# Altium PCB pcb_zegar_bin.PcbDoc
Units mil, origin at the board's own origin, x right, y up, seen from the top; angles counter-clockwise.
Board outline 4065 x 2637.8 mil, 2 copper layers (Top Layer, Bottom Layer); 55 components, 35 nets, 155 pads, 4 vias.
Unrouted connection lines stored in the file: 2.
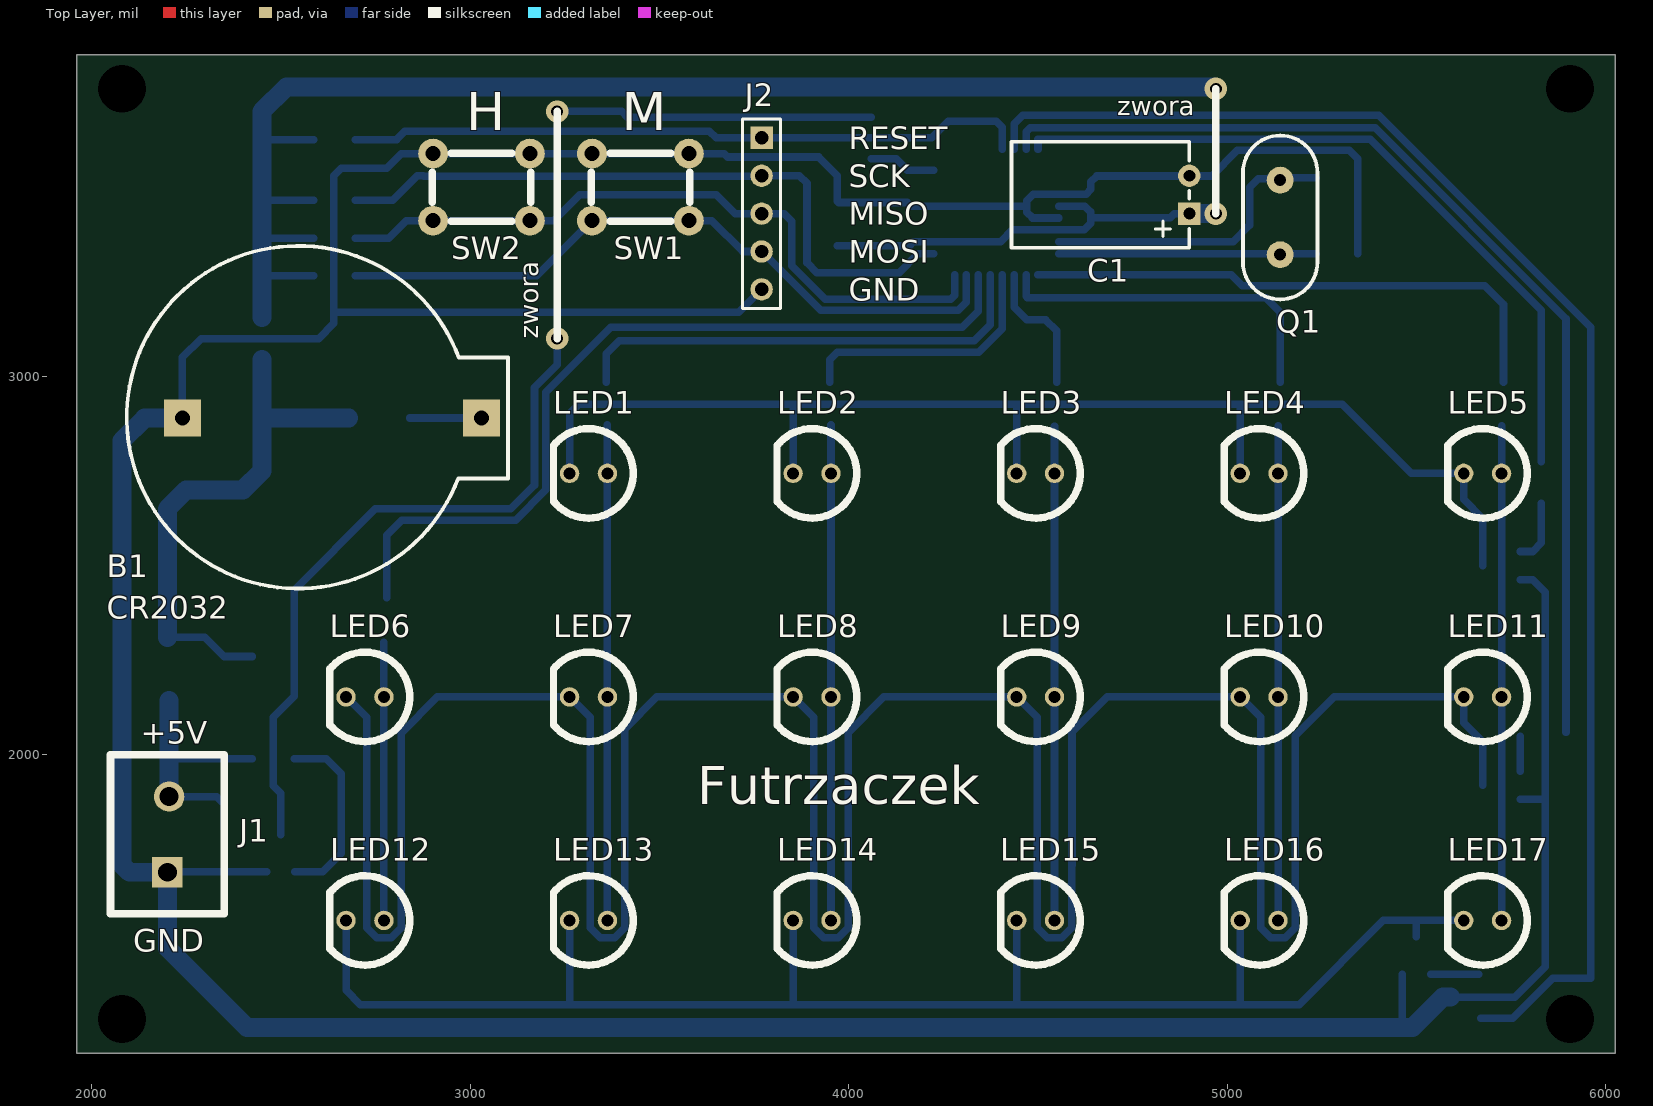
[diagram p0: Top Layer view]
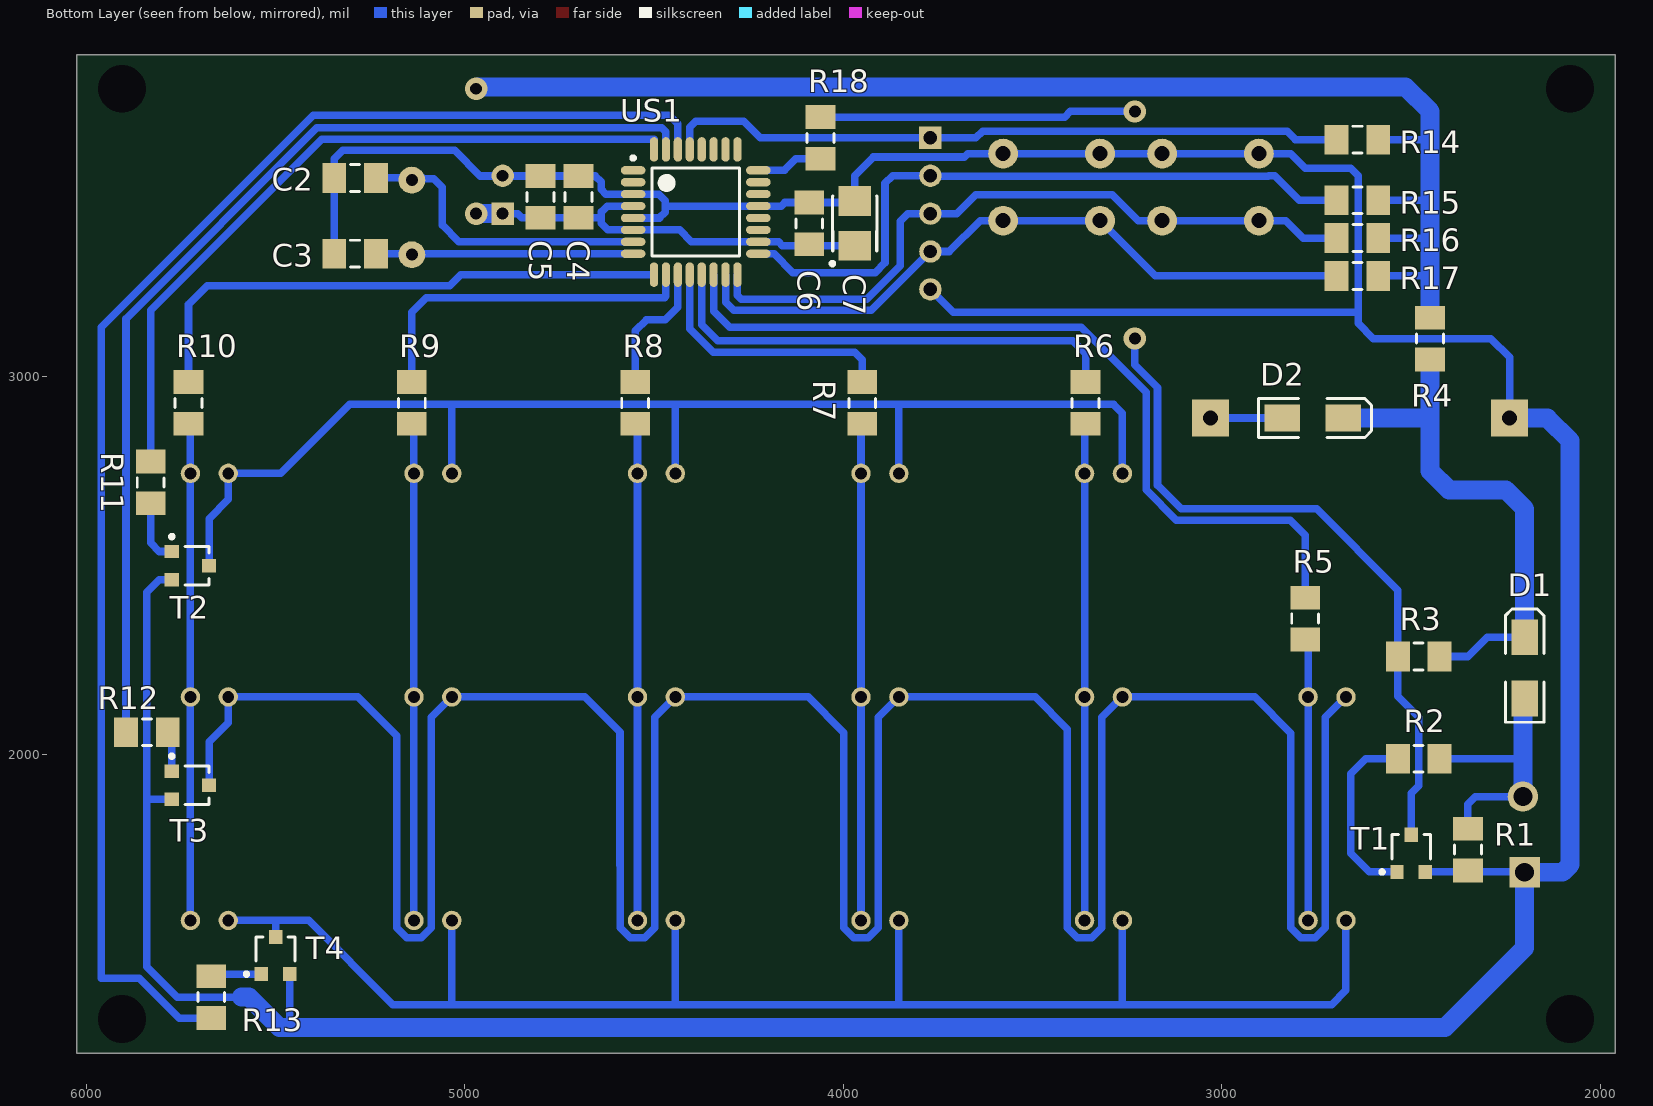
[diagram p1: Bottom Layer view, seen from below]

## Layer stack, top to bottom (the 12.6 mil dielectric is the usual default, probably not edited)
Top Layer: signal copper 1.4
Dielectric: dielectric 12.6, FR-4, Dk 4.8
Bottom Layer: signal copper 1.4

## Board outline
1960.51,1212.2 1960.51,3850 6025.51,3850 6025.51,1212.2

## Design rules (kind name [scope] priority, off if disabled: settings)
Clearance [All] p1: gap=10
PolygonConnect [All] p1: connectstyle=Relief reliefconductorwidth=10 reliefentries=4 polygonreliefangle="90 Angle"
RoutingVias [All] p1: holewidth=28 width=50 viastyle="Through Hole" minholewidth=28 minwidth=50 maxholewidth=28 maxwidth=50
SilkscreenOverComponentPads [All] p1: minsilkscreentomaskgap=10
SolderMaskExpansion [All] p1: expansion=4
Width [All] p1: maxlimit=100 minlimit=10 preferedwidth=20
27 further rules are at their usual default settings.

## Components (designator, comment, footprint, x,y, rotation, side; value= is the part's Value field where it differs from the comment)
B1 "CR2032" "CR20xx THT" 2550,2890 r0 top
C1 "220u/16V" "2,5/7mm le抗cy elektrolit" 4900,3480 r90 top
C2 "18p" MELF-1206 5290,3524.25 r180 bottom
C3 "18p" MELF-1206 5290,3324.25 r180 bottom
C4 "18p" MELF-1206 4700,3474.25 r270 bottom
C5 "100n" MELF-1206 4800,3474.25 r270 bottom
C6 "100n" MELF-1206 4090,3404.25 r270 bottom
C7 "22u/16V B" "Tantal B 3528-1411" 3970,3404.25 r90 bottom
D1 "BYS10-45" SMA 2200,2230 r90 bottom
D2 "BYS10-45" SMA 2760,2890 r180 bottom
J1 "ARK2" "ARK2 5mm" 2200,1790 r90 top
J2 "Header 5" HDR1X5 3770,3630 r270 top
LED1 "red" "LED 5mm" 3312.76,2743.86 r0 top
LED2 "red" "LED 5mm" 3903.31,2743.86 r0 top
LED3 "red" "LED 5mm" 4493.86,2743.86 r0 top
LED4 "red" "LED 5mm" 5084.41,2743.86 r0 top
LED5 "red" "LED 5mm" 5674.96,2743.86 r0 top
LED6 "green" "LED 5mm" 2722.2,2153.31 r0 top
LED7 "green" "LED 5mm" 3312.76,2153.31 r0 top
LED8 "green" "LED 5mm" 3903.31,2153.31 r0 top
LED9 "green" "LED 5mm" 4493.86,2153.31 r0 top
LED10 "green" "LED 5mm" 5084.41,2153.31 r0 top
LED11 "green" "LED 5mm" 5674.96,2153.31 r0 top
LED12 "yellow" "LED 5mm" 2722.2,1562.76 r0 top
LED13 "yellow" "LED 5mm" 3312.76,1562.76 r0 top
LED14 "yellow" "LED 5mm" 3903.31,1562.76 r0 top
LED15 "yellow" "LED 5mm" 4493.86,1562.76 r0 top
LED16 "yellow" "LED 5mm" 5084.41,1562.76 r0 top
LED17 "yellow" "LED 5mm" 5674.96,1562.76 r0 top
Q1 "4MHz" "kwarc 5mm" 5140,3420 r90 top
R1 "4,7k" MELF-1206 2350,1750 r90 bottom
R2 "4,7k" MELF-1206 2480,1990 r180 bottom
R3 "4,7k" MELF-1206 2480,2260 r180 bottom
R4 "0" MELF-1206 2450,3100 r270 bottom
R5 "180" MELF-1206 2780,2360 r90 bottom
R6 "180" MELF-1206 3360,2930 r90 bottom
R7 "180" MELF-1206 3950,2930 r90 bottom
R8 "180" MELF-1206 4550,2930 r90 bottom
R9 "180" MELF-1206 5140,2930 r90 bottom
R10 "180" MELF-1206 5730,2930 r90 bottom
R11 "4,7k" MELF-1206 5830,2720 r90 bottom
R12 "4,7k" MELF-1206 5840,2060 r0 bottom
R13 "4,7k" MELF-1206 5670,1360 r270 bottom
R14 "4,7k" MELF-1206 2641.81,3625.43 r180 bottom
R15 "4,7k" MELF-1206 2641.81,3465.43 r180 bottom
R16 "4,7k" MELF-1206 2641.81,3365.43 r180 bottom
R17 "4,7k" MELF-1206 2641.81,3265.43 r180 bottom
R18 "0" MELF-1206 4060,3630 r270 bottom
SW1 "sw 6x6" "tact switch 6x6" 3450,3500 r180 top
SW2 "sw 6x6" "tact switch 6x6" 3030,3500 r180 top
T1 "BC847" 318-08 2500,1740 r180 bottom
T2 "BC847" 318-08 5724.96,2500 r270 bottom
T3 "BC847" 318-08 5724.96,1920 r270 bottom
T4 "BC847" 318-08 5500,1470 r180 bottom
US1 "ATmega48V-10AU" 32A_N 4390,3434.25 r180 bottom

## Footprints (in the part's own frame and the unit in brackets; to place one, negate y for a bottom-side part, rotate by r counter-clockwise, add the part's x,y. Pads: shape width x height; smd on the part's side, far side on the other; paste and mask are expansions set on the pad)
"2,5/7mm le抗cy elektrolit" [mm]
  rect 1.5x1.5 hole 0.8: 1(-1.27,0)
  round 1.5 hole 0.8: 2(1.27,0)
  silkscreen extent -3.56,0 3.56,11.94
32A_N [mm] "Thin QFP, 32-Leads, Body 7x7mm, Pitch 0.8mm, IPC Medium Density"
  oval 1.65x0.55 smd: 1(-4.2,2.8) 2(-4.2,2) 3(-4.2,1.2) 4(-4.2,0.4) 5(-4.2,-0.4) 6(-4.2,-1.2) 7(-4.2,-2) 8(-4.2,-2.8) 17(4.2,-2.8) 18(4.2,-2) 19(4.2,-1.2) 20(4.2,-0.4) 21(4.2,0.4) 22(4.2,1.2) 23(4.2,2) 24(4.2,2.8)
  oval 0.55x1.65 smd: 9(-2.8,-4.2) 10(-2,-4.2) 11(-1.2,-4.2) 12(-0.4,-4.2) 13(0.4,-4.2) 14(1.2,-4.2) 15(2,-4.2) 16(2.8,-4.2) 25(2.8,4.2) 26(2,4.2) 27(1.2,4.2) 28(0.4,4.2) 29(-0.4,4.2) 30(-1.2,4.2) 31(-2,4.2) 32(-2.8,4.2)
  silkscreen extent -4.33,-2.95 2.95,3.75, body extent -3.5,-3.5 3.5,3.5, height 1.2
318-08 [mm] "SOT-23; 3 Leads; Body 3.0 x 2.6 mm, inc. leads (LxW max)"
  rect 0.9x0.95 smd: 1(-0.95,-1.25) 2(0.95,-1.25) 3(0,1.25)
  silkscreen extent -2.08,-1.37 1.3,1.25
"ARK2 5mm" [mil]
  rect 80x80 hole 50: 1(-100,0)
  round 80 hole 50: 2(100,-5)
  silkscreen extent -210,-150 210,150, body extent -220,-160 220,160, height 394
"CR20xx THT" [mm]
  rect 2.5x2.5 hole 1: 1(12.192,0) 2(-7.874,0)
  silkscreen extent -11.61,-11.44 13.97,11.55
HDR1X5 [mm] "Connector; Header; 5 Position"
  rect 1.5x1.5 hole 0.9: 1(0,0)
  round 1.5 hole 0.9: 2(2.54,0) 3(5.08,0) 4(7.62,0) 5(10.16,0)
  silkscreen extent -1.27,-1.27 11.43,1.27
"kwarc 5mm" [mm]
  round 1.8 hole 0.8: 1(-2.5,0) 2(2.5,0)
  silkscreen extent -5.5,-2.5 5.5,2.5
"LED 5mm" [mm]
  round 1.3 hole 0.8: A(1.27,0) K(-1.27,0)
  silkscreen extent -2.35,-3 3,3
MELF-1206 [mm] "Metal Electrode Face (MELF) Resistor; Body 3.2 x 1.8 mm (LxDia)"
  rect 1.6x2 smd: 1(-1.4,0) 2(1.4,0)
  silkscreen extent -0.3,-0.9 0.3,0.9, body extent -2.3,-1.1 2.3,1.1, height 1.85
SMA [mm] "DO-214-AC/SMA; 2 C-Bend Leads; Body 5 x 2.7 mm, inc. leads (LxW)"
  rect 2.4x1.8 smd: 1(-2.05,0) 2(2.05,0)
  silkscreen extent -3.65,-1.3 3.95,1.3
"tact switch 6x6" [mm]
  round 2 hole 1: 1(3.25,2.25) 2(3.25,-2.25) 3(-3.25,2.25) 4(-3.25,-2.25)
  silkscreen extent -3.3,-2.29 3.3,2.29
"Tantal B 3528-1411" [mm] "Capacitor, SM Tantalum; Body 3.5 x 2.8 mm (LxW typ)"
  rect 2x2.2 smd: 1(-1.5,0) 2(1.5,0)
  silkscreen extent -2.82,-1.5 1.85,1.63, body extent -2.6,-1.2 2.6,1.2, height 2.5

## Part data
B1: library part BAT
C1 C7: library part "kond biegunowy", "Polarized Capacitor"
C2 C3 C4 C5 C6: library part kondensator
D1 D2: library part 10MQ060N, "Schottky Rectifier"
J2: "Header, 5-Pin"
LED1 LED2 LED3 LED4 LED5 LED6 LED7 LED8 LED9 LED10 LED11 LED12 LED13 LED14 LED15 LED16 LED17: library part LED
Q1: library part kwarc
R1 R2 R3 R4 R5 R6 R7 R8 R9 R10 R11 R12 R13 R14 R15 R16 R17 R18: library part rezystor
SW1 SW2: library part switch
T1 T2 T3 T4: library part BC847ALT1, "General Purpose Transistor NPN Silicon"
US1: library part ATmega8-16AC, "8-Bit AVR Microcontroller with 8K Bytes of In-System Programmable Flash Memory"

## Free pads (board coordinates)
  round 0 hole 125.98: 0(2080.51,1302.2) 0(2080.51,3760) 0(5905.51,1302.2) 0(5905.51,3760)

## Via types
v1: diameter 59.06, hole 31.5, Top Layer to Bottom Layer, 4 vias

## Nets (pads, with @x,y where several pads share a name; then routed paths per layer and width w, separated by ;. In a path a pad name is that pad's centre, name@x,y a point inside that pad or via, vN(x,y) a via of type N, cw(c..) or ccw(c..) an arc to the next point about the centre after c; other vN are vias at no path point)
GND: B1.2 C1.2 C2.1 C3.1 C4.1 C5.1 C6.1 C7.2 J1.1 J2.5 R1.1 SW1.2 SW1.4 SW2.2 SW2.4 T1.2 T2.2 T3.2 T4.2 US1.3 US1.5 US1.21 | length 12382.3
  Bottom Layer w20: J1.1@2200.79,1690.79 T1.2 ; B1.2 2240,3050 2290,3100 2600,3100 2640,3140 2640,3170 ; J2.5 3710,3170 2640,3170 ; US1.5 4485.75,3418.5 4470,3434.25 4470,3454.25 ; C3.1 C2.1 5345.12,3574.88 5323.02,3596.98 5026.98,3596.98 4959.37,3529.37 C5.1 C4.1 4655.12,3529.37 4640,3514.25 4640,3494.25 4627.24,3481.5 US1.3 4487.24,3481.5 4470,3464.25 4470,3454.25 ; 5462.6,1297.4 T4.2 ; 5570,1360 5760,1360 5840,1440 5840,2430 5807.4,2462.6 T2.2 ; T3.2 5837.4,1882.6 ; 2640,3170 2640,3530 2660,3550 2780,3550 2818.58,3588.58 SW2.2 SW2.4 SW1.2 SW1.4 3671.42,3588.58 3680.47,3579.53 3920.47,3579.53 3970,3530 C7.2 3973.94,3459.37 C6.1 4154.88,3459.37 4164.25,3450 US1.21 4465.75,3450 4470,3454.25
  Bottom Layer w50: B1.2 2140,2890 2080,2830 2080,1710 2100,1690 J1.1 2200,1490 2410,1280 5490,1280 5570,1360 5590,1360
H: R11.2 US1.32 | length 1944.3
  Bottom Layer w20: US1.32 4500.24,3626.98 5378.16,3626.98 5830,3175.15 R11.2
M: R12.2 US1.31 | length 2778.6
  Bottom Layer w20: US1.31 4469.41,3600.28 4469.41,3646.39 4480,3656.98 5390.59,3656.98 5895.12,3152.46 R12.2
NetB1_1: B1.1 D2.1 | length 189.3
  Bottom Layer w20: D2.1 B1.1
NetC2_2: C2.2 Q1.2 US1.7 | length 808
  Bottom Layer w20: US1.7 5015.51,3355.51 5060,3400 5060,3500 5082.68,3522.68 5110,3522.68 5111.57,3524.25 C2.2
NetC3_2: C3.2 Q1.1 US1.8 | length 679.5
  Bottom Layer w20: US1.8 C3.2@5234.88,3324.02
NetD1_1: D1.1 J1.2 R1.2 R2.2 | length 692.3
  Bottom Layer w20: J1.2 2330,1890 2350,1870 R1.2 ; 2205,1990 R2.2
  Bottom Layer w50: J1.2 2205,1990 D1.1@2205,2144.29
NetD1_2: D1.2 D2.2 R3.2 R4.2 | length 1400.8
  Bottom Layer w20: D1.2 2299.29,2310.71 2350,2260 R3.2
  Bottom Layer w50: D1.2 2200,2650 2250,2700 2400,2700 2450,2750 2450,2890 ; R4.2 2450,2890 ; D2.2 2450,2890
NetJ2_1: J2.1 R14.1 US1.29 | length 1809.3
  Bottom Layer w20: R14.1 2805.43,3625.43 2827.95,3647.95 3632.05,3647.95 3650,3630 J2.1 4219.06,3630 4263.31,3674.25 4390,3674.25 4405.75,3658.5 US1.29
NetJ2_2: J2.2 R15.1 US1.17 | length 1804.7
  Bottom Layer w20: R15.1 2795.43,3465.43 2860,3530 2876.67,3530 2877.46,3529.21 3769.21,3529.21 J2.2 3870,3530 3890,3510 3890,3300 3915.75,3274.25 4133.31,3274.25 4183.07,3324.02 US1.17
NetJ2_3: J2.3 R16.1 SW2.1 SW2.3 US1.16 | length 1872.3
  Bottom Layer w20: R16.1 2785.43,3365.43 2831.42,3411.42 3221.42,3411.42 3290,3480 3650,3480 3700,3430 J2.3 3830,3430 3850,3410 3850,3292.43 3938.17,3204.25 4270,3204.25 4279.76,3214.02 US1.16
NetJ2_4: J2.4 R17.1 SW1.1 SW1.3 US1.15 | length 1855.2
  Bottom Layer w20: R17.1 3175.43,3265.43 3321.42,3411.42 3638.58,3411.42 3720,3330 J2.4 3925.75,3174.25 4290,3174.25 4311.26,3195.51 US1.15
NetLED1_A: LED1.A LED7.A LED13.A R6.1 | length 1309.4
  Bottom Layer w20: LED13.A LED7.A LED1.A R6.1@3362.76,2872.13
NetLED1_K: LED1.K LED2.K LED3.K LED4.K LED5.K T2.3 | length 3407.4
  Bottom Layer w20: LED1.K 3262.76,2902.76 3286.38,2926.38 5303.62,2926.38 5486.14,2743.86 LED5.K 5624.96,2675.04 5675.75,2624.25 T2.3 ; LED2.K 3853.31,2923.07 ; LED3.K 4443.86,2922.52 ; LED4.K 5034.41,2921.97
NetLED2_A: LED2.A LED8.A LED14.A R7.1 | length 1308.8
  Bottom Layer w20: LED14.A LED8.A LED2.A R7.1@3953.31,2871.57
NetLED3_A: LED3.A LED9.A LED15.A R8.1 | length 1306
  Bottom Layer w20: LED15.A LED9.A LED3.A R8.1@4543.86,2868.74
NetLED4_A: LED4.A LED10.A LED16.A R9.1 | length 1306.5
  Bottom Layer w20: LED16.A LED10.A LED4.A R9.1@5134.41,2869.29
NetLED5_A: LED5.A LED11.A LED17.A R10.1 | length 1307.1
  Bottom Layer w20: LED17.A LED11.A LED5.A R10.1@5724.96,2869.84
NetLED6_A: LED6.A LED12.A R5.1 | length 734.3
  Bottom Layer w20: LED12.A LED6.A R5.1@2772.2,2297.09
NetLED6_K: LED6.K LED7.K LED8.K LED9.K LED10.K LED11.K T3.3 | length 8975.8
  Bottom Layer w20: LED6.K 2726.61,2098.9 2726.61,1543.87 2753.32,1517.17 2791.09,1517.17 2817.8,1543.87 2817.8,2057.8 2913.31,2153.31 LED7.K 3317.17,2098.9 3317.17,1543.87 3343.87,1517.17 3381.64,1517.17 3408.35,1543.87 3408.35,2068.35 3493.31,2153.31 LED8.K 3907.72,2098.9 3907.72,1543.87 3934.42,1517.17 3972.19,1517.17 3998.9,1543.87 3998.9,2058.9 4093.31,2153.31 LED9.K ; LED9.K@4443.58,2153.58 LED9.K ; 4589.45,1708.35 4589.45,1543.87 4562.74,1517.17 4524.97,1517.17 4498.27,1543.87 4498.27,2098.9 LED9.K ; 4590,1708.9 4590,2060 4683.31,2153.31 LED10.K 5088.82,2098.9 5088.82,1543.87 5115.53,1517.17 5153.29,1517.17 5180,1543.87 5180,2050 5283.31,2153.31 LED11.K 5624.96,2085.04 5675.75,2034.25 T3.3
NetLED12_K: LED12.K LED13.K LED14.K LED15.K LED16.K LED17.K T4.3 | length 4163.6
  Bottom Layer w20: LED12.K 2672.2,1377.8 2710,1340 5190,1340 5412.76,1562.76 5500,1562.76 ; 3262.76,1342.76 LED13.K ; 3853.31,1343.31 LED14.K ; 4443.86,1346.14 LED15.K ; 5034.41,1344.41 LED16.K ; T4.3 5500,1562.76 ; LED17.K 5500,1562.76
NetR2_1: R2.1 T1.1 | length 494.4
  Bottom Layer w20: R2.1 2620,1990 2660,1950 2660,1740 2610.79,1690.79 T1.1
NetR11_1: R11.1 T2.1 | length 170.1
  Bottom Layer w20: T2.1 5807.4,2537.4 5830,2560 R11.1
NetR12_1: R12.1 T3.1 | length 91.9
  Bottom Layer w20: T3.1 R12.1@5774.17,2049.29
NetR13_1: R13.1 T4.1 | length 126.9
  Bottom Layer w20: T4.1 R13.1@5664.33,1420.79
NetR18_2: R18.2 US1.24 | length 177.2
  Bottom Layer w20: R18.2 4125.12,3574.88 4155.51,3544.49 US1.24
S: R13.2 US1.30 | length 3885.3
  Bottom Layer w20: US1.30 4437.24,3667.24 4460,3690 5400,3690 5960,3130 5960,1410 5860,1410 5754.88,1304.88 R13.2
SUPPLY: R3.1 R18.1 T1.3 | length 2675.4
  Bottom Layer w20: T1.3 2500,1899.01 2480,1919.01 2480,2100 2535.12,2155.12 R3.1 2535.12,2435.12 2750,2650 2770,2650 3107.57,2650 3170,2712.43 3170,2970.39 3230,3030.39 v1(3230,3100) ; v1(3230,3700) 3400,3700 3414.88,3685.12 R18.1
VCC: C1.1 C4.2 C5.2 C6.2 C7.1 R4.1 R14.2 R15.2 R16.2 R17.2 US1.4 US1.6 US1.18 | length 4773.7
  Bottom Layer w20: 2454.57,3265.43 R17.2 ; 2454.57,3465.43 R15.2 ; 2454.57,3625.43 R14.2 ; 2455.43,3365.43 R16.2 ; C7.1 4160.94,3345.2 4171.26,3355.51 US1.18 4401.26,3355.51 4432.76,3387.01 US1.6 4622.76,3387.01 4640,3404.25 4640,3414.25 ; US1.4 4624.25,3450 4640,3434.25 4640,3414.25 ; C1.1 4860,3430 4849.13,3419.13 C5.2 C4.2 4644.88,3419.13 4640,3414.25
  Bottom Layer w50: R4.1 2450,3700 2515,3765 4965,3765 v1(4970,3760) ; C1.1 v1(4970,3430)
X1: R10.2 US1.9 | length 1467.3
  Bottom Layer w20: US1.9 5011.1,3268.9 5040,3240 5680,3240 5730,3190 R10.2
X2: R9.2 US1.10 | length 930.9
  Bottom Layer w20: US1.10 4468.74,3211.26 4472.28,3207.72 5102.28,3207.72 5140,3170 R9.2
X4: R8.2 US1.11 | length 359.8
  Bottom Layer w20: US1.11 4437.24,3182.76 4470,3150 4520,3150 4550,3120 R8.2
X8: R7.2 US1.12 | length 691.8
  Bottom Layer w20: R7.2 3950,3044.25 3970,3064.25 4344.25,3064.25 4405.75,3125.75 US1.12
X16: R6.2 US1.13 | length 1253.1
  Bottom Layer w20: R6.2 3360,3060 3394.25,3094.25 4331.83,3094.25 4374.25,3136.68 US1.13
X32: R5.2 US1.14 | length 2220.4
  Bottom Layer w20: R5.2 2780,2580 2820,2620 3120,2620 3200,2700 3200,2957.97 3372.03,3130 4300,3130 4342.76,3172.76 US1.14
pads on no net: US1.1 US1.2 US1.19 US1.20 US1.22 US1.23 US1.25 US1.26 US1.27 US1.28

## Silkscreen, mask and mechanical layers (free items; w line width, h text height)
Top Overlay:
  lines w20: 3230,3100 3230,3700 ; 4970,3430 4970,3760
  text "zwora" at 4710,3690 h50
  text "H" at 2990,3650 h100
  text "M" at 3400,3650 h100
  text "RESET" at 4000,3600 h60
  text "SCK" at 4000,3500 h60
  text "MISO" at 4000,3400 h60
  text "MOSI" at 4000,3300 h60
  text "GND" at 4000,3200 h60
  text "zwora" at 3180,3100 h50 r90
  text "CR2032" at 2040,2360 h60
  text "+5V" at 2130,2030 h60
  text "Futrzaczek" at 3600,1870 h100
  text "GND" at 2110,1480 h60
Mechanical 1:
  the board outline again, w5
